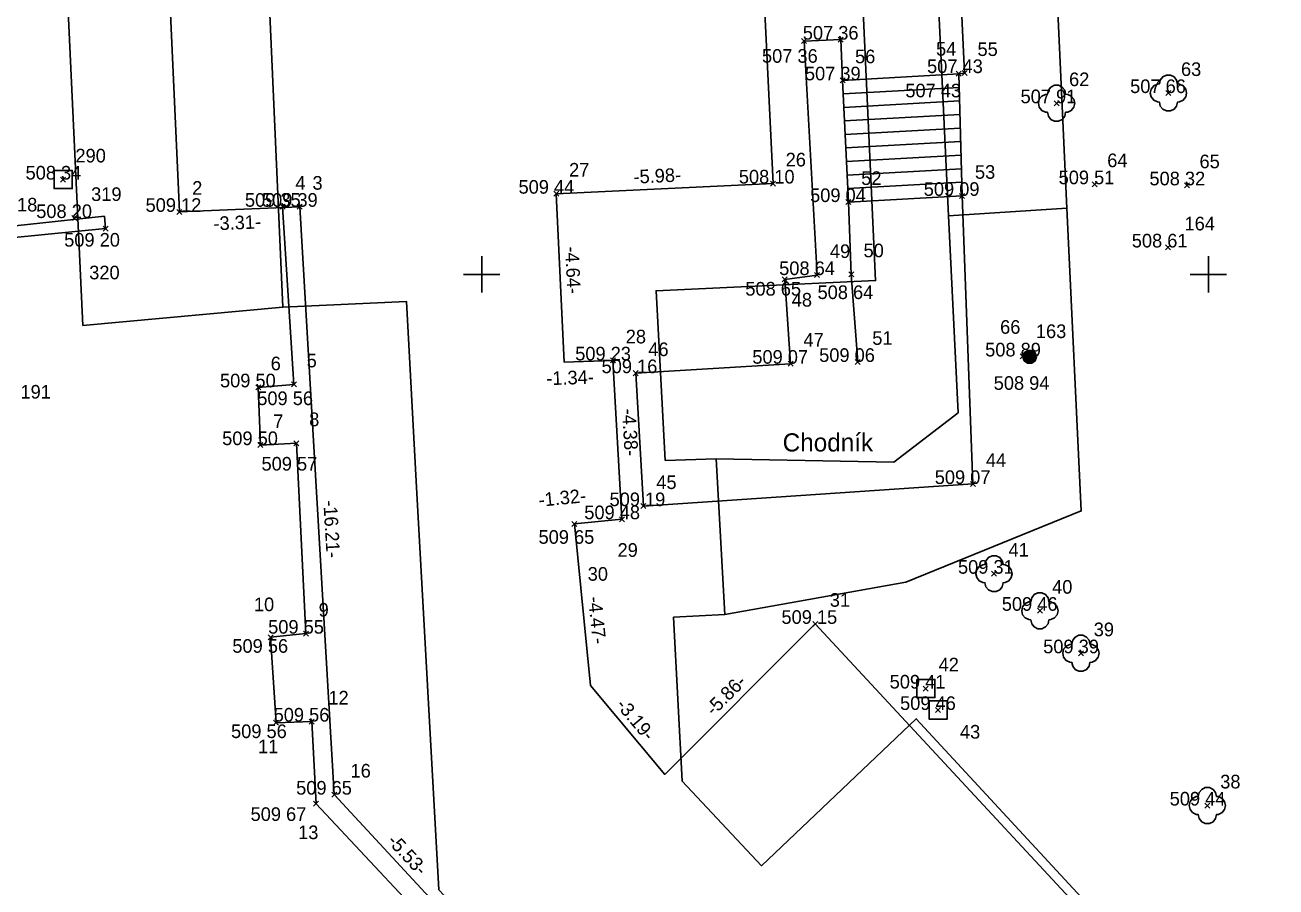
# Model space of a CAD drawing. Extents: x -408550 to -407654, y -1233019 to -1231230.
# Drawn here: x -407992.57 to -407958.14, y -1232056.86 to -1232033.14 of the extents above; entities that cross this region are included whole.
import ezdxf

# ---------------------------------------------------------------- set-up
doc = ezdxf.new("R2010")
doc.units = 0
for name, color, linetype in [('Level 1', 7, 'Continuous'), ('Level 11', 7, 'Continuous'), ('Level 16', 7, 'Continuous'), ('Level 20', 7, 'Continuous'), ('Level 23', 7, 'Continuous'), ('Level 26', 7, 'Continuous'), ('Level 28', 7, 'Continuous'), ('Level 40', 7, 'Continuous'), ('Level 45', 7, 'Continuous'), ('Level 5', 7, 'Continuous')]:
    doc.layers.add(name, color=color, linetype=linetype)

msp = doc.modelspace()

# ---------------------------------------------------------------- linework, layer by layer
at = {"layer": 'Level 1'}
for p, q in [((-407980, -1232039.5), (-407980, -1232040.5)), ((-407960, -1232039.5), (-407960, -1232040.5)), ((-407980.5, -1232040), (-407979.5, -1232040)), ((-407960.5, -1232040), (-407959.5, -1232040))]:
    msp.add_line(p, q, dxfattribs=at)
for points in [[(-407983.55, -1232015.52), (-407983.6, -1232014.52), (-407981.73, -1232014.41), (-407981.67, -1232015.42), (-407970.32, -1232014.9), (-407969.16, -1232040.17), (-407975.2, -1232040.45), (-407974.95, -1232045.12), (-407973.55, -1232045.08), (-407973.31, -1232049.36), (-407974.72, -1232049.44), (-407974.48, -1232053.95), (-407972.3, -1232056.28), (-407968.04, -1232052.23), (-407946.92, -1232075.07), (-407959.14, -1232086.36), (-407980.2, -1232063.57), (-407977.4, -1232060.97), (-407981.18, -1232056.94), (-407981.8, -1232045.69), (-407982.07, -1232040.75), (-407985.47, -1232040.9), (-407986.59, -1232015.66)], [(-407983.6, -1232014.52), (-407983.55, -1232015.52), (-407986.59, -1232015.66), (-407985.47, -1232040.9), (-407982.07, -1232040.75), (-407981.8, -1232045.69), (-407981.18, -1232056.94), (-407977.4, -1232060.97), (-407980.2, -1232063.57), (-407959.14, -1232086.36), (-407946.92, -1232075.07), (-407968.04, -1232052.23), (-407972.3, -1232056.28), (-407974.48, -1232053.95), (-407974.72, -1232049.44), (-407973.31, -1232049.36), (-407973.55, -1232045.08), (-407974.95, -1232045.12), (-407975.2, -1232040.45), (-407969.16, -1232040.17), (-407970.32, -1232014.9), (-407981.67, -1232015.42), (-407981.73, -1232014.41)]]:
    msp.add_lwpolyline(points, close=True, dxfattribs=at)
at = {"layer": 'Level 11'}
msp.add_lwpolyline([(-407989.46, -1232013.01), (-407973.21, -1232012.23), (-407971.98, -1232037.5), (-407977.95, -1232037.78), (-407977.733, -1232042.415), (-407976.39, -1232042.37), (-407976.14, -1232046.74), (-407977.45, -1232046.87), (-407977.009, -1232051.318), (-407974.962, -1232053.765), (-407970.82, -1232049.62), (-407949.71, -1232072.37), (-407961.89, -1232083.71), (-407983.01, -1232060.92), (-407980.3, -1232058.38), (-407984.06, -1232054.32), (-407985.01, -1232038.14), (-407988.32, -1232038.28)], close=True, dxfattribs=at)
at = {"layer": 'Level 16'}
for p, q in [((-407970.07, -1232034.66), (-407966.87, -1232034.48)), ((-407966.86, -1232034.853), (-407970.052, -1232035.032)), ((-407966.85, -1232035.227), (-407970.034, -1232035.404)), ((-407966.84, -1232035.6), (-407970.017, -1232035.777)), ((-407966.83, -1232035.973), (-407969.999, -1232036.149)), ((-407966.82, -1232036.347), (-407969.981, -1232036.521)), ((-407966.81, -1232036.72), (-407969.963, -1232036.893)), ((-407966.8, -1232037.093), (-407969.946, -1232037.266)), ((-407966.79, -1232037.467), (-407969.928, -1232037.638)), ((-407969.91, -1232038.01), (-407966.78, -1232037.84))]:
    msp.add_line(p, q, dxfattribs=at)
for points in [[(-407975.55, -1232046.38), (-407966.48, -1232045.77), (-407966.78, -1232037.84), (-407966.87, -1232034.48), (-407966.71, -1232034.46), (-407967.34, -1232021.13), (-407968.99, -1231990.5), (-407969.06, -1231986.9)], [(-407975.55, -1232046.38), (-407975.76, -1232042.72), (-407971.5, -1232042.46), (-407971.66, -1232040.14), (-407970.77, -1232040.02), (-407971.13, -1232033.58), (-407970.12, -1232033.54), (-407970.07, -1232034.66), (-407969.91, -1232038.01), (-407969.83, -1232040), (-407969.65, -1232042.41)], [(-407985.48, -1232038.14), (-407985.17, -1232043.03), (-407986.15, -1232043.11), (-407986.09, -1232044.7), (-407985.1, -1232044.65), (-407984.84, -1232049.89), (-407985.81, -1232049.99), (-407985.66, -1232052.34), (-407984.68, -1232052.31), (-407984.56, -1232054.57), (-407980.66, -1232058.74)]]:
    msp.add_lwpolyline(points, dxfattribs=at)
for points in [[(-407994.84, -1232017.97), (-407994.55, -1232017.75), (-407994.47, -1232018.24), (-407994.26, -1232023.61), (-407993.53, -1232038.74), (-407990.383, -1232038.402), (-407990.35, -1232038.74), (-407993.79, -1232039.08), (-407994.06, -1232034.84), (-407994.54, -1232023.67)], [(-407966.87, -1232034.48), (-407970.07, -1232034.66), (-407969.91, -1232038.01), (-407966.78, -1232037.84)]]:
    msp.add_lwpolyline(points, close=True, dxfattribs=at)
at = {"layer": 'Level 20'}
for points in [[(-407991.77, -1232037.14), (-407991.27, -1232037.14), (-407991.27, -1232037.64), (-407991.77, -1232037.64)], [(-407968.03, -1232051.15), (-407967.53, -1232051.15), (-407967.53, -1232051.65), (-407968.03, -1232051.65)], [(-407967.69, -1232051.74), (-407967.19, -1232051.74), (-407967.19, -1232052.24), (-407967.69, -1232052.24)]]:
    msp.add_lwpolyline(points, close=True, dxfattribs=at)
at = {"layer": 'Level 23'}
for points in [[(-407971.061, -1232033.649), (-407971.199, -1232033.511)], [(-407971.199, -1232033.649), (-407971.061, -1232033.511)], [(-407970.051, -1232033.609), (-407970.189, -1232033.471)], [(-407970.189, -1232033.609), (-407970.051, -1232033.471)], [(-407966.801, -1232034.549), (-407966.939, -1232034.411)], [(-407966.939, -1232034.549), (-407966.801, -1232034.411)], [(-407966.641, -1232034.529), (-407966.779, -1232034.391)], [(-407966.779, -1232034.529), (-407966.641, -1232034.391)], [(-407970.001, -1232034.729), (-407970.139, -1232034.591)], [(-407970.139, -1232034.729), (-407970.001, -1232034.591)], [(-407964.111, -1232035.359), (-407964.249, -1232035.221)], [(-407964.249, -1232035.359), (-407964.111, -1232035.221)], [(-407961.031, -1232035.079), (-407961.169, -1232034.941)], [(-407961.169, -1232035.079), (-407961.031, -1232034.941)], [(-407991.451, -1232037.459), (-407991.589, -1232037.321)], [(-407991.589, -1232037.459), (-407991.451, -1232037.321)], [(-407971.911, -1232037.569), (-407972.049, -1232037.431)], [(-407972.049, -1232037.569), (-407971.911, -1232037.431)], [(-407963.061, -1232037.589), (-407963.199, -1232037.451)], [(-407963.199, -1232037.589), (-407963.061, -1232037.451)], [(-407960.521, -1232037.619), (-407960.659, -1232037.481)], [(-407960.659, -1232037.619), (-407960.521, -1232037.481)], [(-407977.881, -1232037.849), (-407978.019, -1232037.711)], [(-407978.019, -1232037.849), (-407977.881, -1232037.711)], [(-407969.841, -1232038.079), (-407969.979, -1232037.941)], [(-407969.979, -1232038.079), (-407969.841, -1232037.941)], [(-407966.711, -1232037.909), (-407966.849, -1232037.771)], [(-407966.849, -1232037.909), (-407966.711, -1232037.771)], [(-407988.251, -1232038.349), (-407988.389, -1232038.211)], [(-407988.389, -1232038.349), (-407988.251, -1232038.211)], [(-407985.411, -1232038.209), (-407985.549, -1232038.071)], [(-407985.549, -1232038.209), (-407985.411, -1232038.071)], [(-407984.941, -1232038.209), (-407985.079, -1232038.071)], [(-407985.079, -1232038.209), (-407984.941, -1232038.071)], [(-407991.141, -1232038.519), (-407991.279, -1232038.381)], [(-407991.279, -1232038.519), (-407991.141, -1232038.381)], [(-407990.281, -1232038.809), (-407990.419, -1232038.671)], [(-407990.419, -1232038.809), (-407990.281, -1232038.671)], [(-407961.041, -1232039.329), (-407961.179, -1232039.191)], [(-407961.179, -1232039.329), (-407961.041, -1232039.191)], [(-407970.701, -1232040.089), (-407970.839, -1232039.951)], [(-407970.839, -1232040.089), (-407970.701, -1232039.951)], [(-407969.761, -1232040.069), (-407969.899, -1232039.931)], [(-407969.899, -1232040.069), (-407969.761, -1232039.931)], [(-407971.591, -1232040.209), (-407971.729, -1232040.071)], [(-407971.729, -1232040.209), (-407971.591, -1232040.071)], [(-407976.321, -1232042.439), (-407976.459, -1232042.301)], [(-407976.459, -1232042.439), (-407976.321, -1232042.301)], [(-407971.431, -1232042.529), (-407971.569, -1232042.391)], [(-407971.569, -1232042.529), (-407971.431, -1232042.391)], [(-407969.581, -1232042.479), (-407969.719, -1232042.341)], [(-407969.719, -1232042.479), (-407969.581, -1232042.341)], [(-407965.041, -1232042.329), (-407965.179, -1232042.191)], [(-407965.179, -1232042.329), (-407965.041, -1232042.191)], [(-407964.851, -1232042.339), (-407964.989, -1232042.201)], [(-407964.989, -1232042.339), (-407964.851, -1232042.201)], [(-407975.691, -1232042.789), (-407975.829, -1232042.651)], [(-407975.829, -1232042.789), (-407975.691, -1232042.651)], [(-407986.081, -1232043.179), (-407986.219, -1232043.041)], [(-407986.219, -1232043.179), (-407986.081, -1232043.041)], [(-407985.101, -1232043.099), (-407985.239, -1232042.961)], [(-407985.239, -1232043.099), (-407985.101, -1232042.961)], [(-407986.021, -1232044.769), (-407986.159, -1232044.631)], [(-407986.159, -1232044.769), (-407986.021, -1232044.631)], [(-407985.031, -1232044.719), (-407985.169, -1232044.581)], [(-407985.169, -1232044.719), (-407985.031, -1232044.581)], [(-407966.411, -1232045.839), (-407966.549, -1232045.701)], [(-407966.549, -1232045.839), (-407966.411, -1232045.701)], [(-407975.481, -1232046.449), (-407975.619, -1232046.311)], [(-407975.619, -1232046.449), (-407975.481, -1232046.311)], [(-407977.381, -1232046.939), (-407977.519, -1232046.801)], [(-407977.519, -1232046.939), (-407977.381, -1232046.801)], [(-407976.071, -1232046.809), (-407976.209, -1232046.671)], [(-407976.209, -1232046.809), (-407976.071, -1232046.671)], [(-407965.831, -1232048.309), (-407965.969, -1232048.171)], [(-407965.969, -1232048.309), (-407965.831, -1232048.171)], [(-407964.571, -1232049.329), (-407964.709, -1232049.191)], [(-407964.709, -1232049.329), (-407964.571, -1232049.191)], [(-407970.751, -1232049.689), (-407970.889, -1232049.551)], [(-407970.889, -1232049.689), (-407970.751, -1232049.551)], [(-407985.741, -1232050.059), (-407985.879, -1232049.921)], [(-407985.879, -1232050.059), (-407985.741, -1232049.921)], [(-407984.771, -1232049.959), (-407984.909, -1232049.821)], [(-407984.909, -1232049.959), (-407984.771, -1232049.821)], [(-407963.441, -1232050.499), (-407963.579, -1232050.361)], [(-407963.579, -1232050.499), (-407963.441, -1232050.361)], [(-407967.711, -1232051.469), (-407967.849, -1232051.331)], [(-407967.849, -1232051.469), (-407967.711, -1232051.331)], [(-407967.371, -1232052.059), (-407967.509, -1232051.921)], [(-407967.509, -1232052.059), (-407967.371, -1232051.921)], [(-407985.591, -1232052.409), (-407985.729, -1232052.271)], [(-407985.729, -1232052.409), (-407985.591, -1232052.271)], [(-407984.611, -1232052.379), (-407984.749, -1232052.241)], [(-407984.749, -1232052.379), (-407984.611, -1232052.241)], [(-407984.491, -1232054.639), (-407984.629, -1232054.501)], [(-407984.629, -1232054.639), (-407984.491, -1232054.501)], [(-407983.991, -1232054.389), (-407984.129, -1232054.251)], [(-407984.129, -1232054.389), (-407983.991, -1232054.251)], [(-407959.961, -1232054.689), (-407960.099, -1232054.551)], [(-407960.099, -1232054.689), (-407959.961, -1232054.551)]]:
    msp.add_lwpolyline(points, dxfattribs=at)
at = {"layer": 'Level 28'}
for points in [[(-407960.6, -1232035.01), (-407960.625, -1232035.118), (-407960.694, -1232035.206), (-407960.794, -1232035.254), (-407960.85, -1232035.26), (-407960.875, -1232035.368), (-407960.944, -1232035.456), (-407961.044, -1232035.504), (-407961.156, -1232035.504), (-407961.256, -1232035.456), (-407961.325, -1232035.368), (-407961.35, -1232035.26), (-407961.406, -1232035.254), (-407961.506, -1232035.206), (-407961.575, -1232035.118), (-407961.6, -1232035.01), (-407961.575, -1232034.902), (-407961.506, -1232034.814), (-407961.406, -1232034.766), (-407961.35, -1232034.76), (-407961.325, -1232034.652), (-407961.256, -1232034.564), (-407961.156, -1232034.516), (-407961.044, -1232034.516), (-407960.944, -1232034.564), (-407960.875, -1232034.652), (-407960.85, -1232034.76), (-407960.794, -1232034.766), (-407960.694, -1232034.814), (-407960.625, -1232034.902)], [(-407963.68, -1232035.29), (-407963.705, -1232035.399), (-407963.774, -1232035.486), (-407963.874, -1232035.534), (-407963.93, -1232035.54), (-407963.955, -1232035.649), (-407964.024, -1232035.736), (-407964.124, -1232035.784), (-407964.236, -1232035.784), (-407964.336, -1232035.736), (-407964.405, -1232035.649), (-407964.43, -1232035.54), (-407964.486, -1232035.534), (-407964.586, -1232035.486), (-407964.655, -1232035.399), (-407964.68, -1232035.29), (-407964.655, -1232035.182), (-407964.586, -1232035.095), (-407964.486, -1232035.046), (-407964.43, -1232035.04), (-407964.405, -1232034.932), (-407964.336, -1232034.845), (-407964.236, -1232034.796), (-407964.124, -1232034.796), (-407964.024, -1232034.845), (-407963.955, -1232034.932), (-407963.93, -1232035.04), (-407963.874, -1232035.046), (-407963.774, -1232035.095), (-407963.705, -1232035.182)], [(-407965.4, -1232048.24), (-407965.425, -1232048.348), (-407965.494, -1232048.436), (-407965.594, -1232048.484), (-407965.65, -1232048.49), (-407965.675, -1232048.598), (-407965.744, -1232048.686), (-407965.844, -1232048.734), (-407965.956, -1232048.734), (-407966.056, -1232048.686), (-407966.125, -1232048.598), (-407966.15, -1232048.49), (-407966.206, -1232048.484), (-407966.306, -1232048.436), (-407966.375, -1232048.348), (-407966.4, -1232048.24), (-407966.375, -1232048.132), (-407966.306, -1232048.044), (-407966.206, -1232047.996), (-407966.15, -1232047.99), (-407966.125, -1232047.882), (-407966.056, -1232047.794), (-407965.956, -1232047.746), (-407965.844, -1232047.746), (-407965.744, -1232047.794), (-407965.675, -1232047.882), (-407965.65, -1232047.99), (-407965.594, -1232047.996), (-407965.494, -1232048.044), (-407965.425, -1232048.132)], [(-407964.14, -1232049.26), (-407964.165, -1232049.368), (-407964.234, -1232049.456), (-407964.334, -1232049.504), (-407964.39, -1232049.51), (-407964.415, -1232049.618), (-407964.484, -1232049.706), (-407964.584, -1232049.754), (-407964.696, -1232049.754), (-407964.796, -1232049.706), (-407964.865, -1232049.618), (-407964.89, -1232049.51), (-407964.946, -1232049.504), (-407965.046, -1232049.456), (-407965.115, -1232049.368), (-407965.14, -1232049.26), (-407965.115, -1232049.152), (-407965.046, -1232049.064), (-407964.946, -1232049.016), (-407964.89, -1232049.01), (-407964.865, -1232048.902), (-407964.796, -1232048.814), (-407964.696, -1232048.766), (-407964.584, -1232048.766), (-407964.484, -1232048.814), (-407964.415, -1232048.902), (-407964.39, -1232049.01), (-407964.334, -1232049.016), (-407964.234, -1232049.064), (-407964.165, -1232049.152)], [(-407963.01, -1232050.43), (-407963.035, -1232050.538), (-407963.104, -1232050.625), (-407963.204, -1232050.674), (-407963.26, -1232050.68), (-407963.285, -1232050.788), (-407963.354, -1232050.875), (-407963.454, -1232050.924), (-407963.566, -1232050.924), (-407963.666, -1232050.875), (-407963.735, -1232050.788), (-407963.76, -1232050.68), (-407963.816, -1232050.674), (-407963.916, -1232050.625), (-407963.985, -1232050.538), (-407964.01, -1232050.43), (-407963.985, -1232050.321), (-407963.916, -1232050.234), (-407963.816, -1232050.186), (-407963.76, -1232050.18), (-407963.735, -1232050.071), (-407963.666, -1232049.984), (-407963.566, -1232049.936), (-407963.454, -1232049.936), (-407963.354, -1232049.984), (-407963.285, -1232050.071), (-407963.26, -1232050.18), (-407963.204, -1232050.186), (-407963.104, -1232050.234), (-407963.035, -1232050.321)], [(-407959.53, -1232054.62), (-407959.555, -1232054.729), (-407959.624, -1232054.816), (-407959.724, -1232054.864), (-407959.78, -1232054.87), (-407959.805, -1232054.979), (-407959.874, -1232055.066), (-407959.974, -1232055.114), (-407960.086, -1232055.114), (-407960.186, -1232055.066), (-407960.255, -1232054.979), (-407960.28, -1232054.87), (-407960.336, -1232054.864), (-407960.436, -1232054.816), (-407960.505, -1232054.729), (-407960.53, -1232054.62), (-407960.505, -1232054.512), (-407960.436, -1232054.425), (-407960.336, -1232054.376), (-407960.28, -1232054.37), (-407960.255, -1232054.262), (-407960.186, -1232054.175), (-407960.086, -1232054.126), (-407959.974, -1232054.126), (-407959.874, -1232054.175), (-407959.805, -1232054.262), (-407959.78, -1232054.37), (-407959.724, -1232054.376), (-407959.624, -1232054.425), (-407959.555, -1232054.512)]]:
    msp.add_lwpolyline(points, close=True, dxfattribs=at)
for points in [[(-407961.112, -1232035.01), (-407961.1, -1232035.01), (-407961.087, -1232035.01)], [(-407964.192, -1232035.29), (-407964.18, -1232035.29), (-407964.168, -1232035.29)], [(-407965.913, -1232048.24), (-407965.9, -1232048.24), (-407965.888, -1232048.24)], [(-407964.652, -1232049.26), (-407964.64, -1232049.26), (-407964.628, -1232049.26)], [(-407963.522, -1232050.43), (-407963.51, -1232050.43), (-407963.498, -1232050.43)], [(-407960.043, -1232054.62), (-407960.03, -1232054.62), (-407960.018, -1232054.62)]]:
    msp.add_lwpolyline(points, dxfattribs=at)
at = {"layer": 'Level 45'}
msp.add_lwpolyline([(-407964.978, -1232042.092), (-407964.862, -1232042.092), (-407964.768, -1232042.16), (-407964.732, -1232042.27), (-407964.768, -1232042.38), (-407964.862, -1232042.448), (-407964.978, -1232042.448), (-407965.072, -1232042.38), (-407965.108, -1232042.27), (-407965.072, -1232042.16), (-407964.978, -1232042.092), (-407964.965, -1232042.105), (-407964.875, -1232042.105), (-407964.815, -1232042.135), (-407965.025, -1232042.135), (-407965.055, -1232042.165), (-407964.785, -1232042.165), (-407964.785, -1232042.195), (-407965.055, -1232042.195), (-407965.071, -1232042.225), (-407964.77, -1232042.225), (-407964.755, -1232042.255), (-407965.085, -1232042.255), (-407965.085, -1232042.285), (-407964.755, -1232042.285), (-407964.767, -1232042.315), (-407965.072, -1232042.315), (-407965.07, -1232042.345), (-407964.767, -1232042.345), (-407964.785, -1232042.375), (-407965.055, -1232042.375), (-407965.025, -1232042.405), (-407964.815, -1232042.405), (-407964.856, -1232042.435), (-407964.983, -1232042.435)], dxfattribs=at)
at = {"layer": 'Level 5'}
for p, q in [((-407966.08, -1231990.2), (-407963.9, -1232038.18)), ((-407967.15, -1232038.39), (-407968.26, -1232014.87)), ((-407990.98, -1232041.41), (-407992.15, -1232016.06)), ((-407963.9, -1232038.18), (-407967.15, -1232038.39)), ((-407985.47, -1232040.9), (-407990.98, -1232041.41))]:
    msp.add_line(p, q, dxfattribs=at)
for points in [[(-407963.9, -1232038.18), (-407963.5, -1232046.51), (-407968.33, -1232048.47), (-407973.31, -1232049.36)], [(-407973.55, -1232045.08), (-407968.66, -1232045.17), (-407966.89, -1232043.81), (-407967.15, -1232038.39)]]:
    msp.add_lwpolyline(points, dxfattribs=at)

# ---------------------------------------------------------------- texts
at = {"layer": 'Level 1'}
for s, rotation, p in [('-5.98-', 2.6929, (-407975.815, -1232037.505)), ('-3.31-', 2.4064, (-407987.376, -1232038.79)), ('-4.64-', 272.6812, (-407977.706, -1232039.238)), ('-1.34-', 1.8908, (-407978.218, -1232043.052)), ('-4.38-', 273.2542, (-407976.138, -1232043.705)), ('-16.21-', 273.3688, (-407984.36, -1232046.229)), ('-1.32-', 5.6723, (-407978.418, -1232046.4)), ('-4.47-', 275.6606, (-407977.074, -1232048.886)), ('-5.86-', 45.0345, (-407973.617, -1232052.172)), ('-3.19-', 309.9235, (-407976.324, -1232051.865)), ('-5.53-', 312.7883, (-407982.623, -1232055.614))]:
    msp.add_text(s, height=0.375, rotation=rotation, dxfattribs=at).set_placement(p)
at = {"layer": 'Level 26'}
for s, p in [('56', (-407969.726, -1232034.19)), ('54', (-407967.497, -1232033.98)), ('55', (-407966.356, -1232033.99)), ('63', (-407960.756, -1232034.54)), ('62', (-407963.836, -1232034.82)), ('290', (-407991.181, -1232036.92)), ('27', (-407977.596, -1232037.31)), ('26', (-407971.636, -1232037.03)), ('64', (-407962.786, -1232037.05)), ('65', (-407960.246, -1232037.08)), ('4', (-407985.128, -1232037.67)), ('3', (-407984.658, -1232037.67)), ('52', (-407969.556, -1232037.54)), ('53', (-407966.426, -1232037.37)), ('319', (-407990.749, -1232037.98)), ('2', (-407987.968, -1232037.81)), ('318', (-407993.067, -1232038.27)), ('164', (-407960.658, -1232038.79)), ('49', (-407970.417, -1232039.55)), ('50', (-407969.492, -1232039.53)), ('320', (-407990.802, -1232040.137)), ('48', (-407971.468, -1232040.888)), ('66', (-407965.734, -1232041.636)), ('163', (-407964.749, -1232041.754)), ('28', (-407976.036, -1232041.9)), ('47', (-407971.146, -1232041.99)), ('51', (-407969.251, -1232041.94)), ('46', (-407975.416, -1232042.25)), ('6', (-407985.808, -1232042.64)), ('5', (-407984.818, -1232042.56)), ('191', (-407992.694, -1232043.42)), ('8', (-407984.748, -1232044.18)), ('7', (-407985.738, -1232044.23)), ('44', (-407966.126, -1232045.3)), ('45', (-407975.196, -1232045.91)), ('29', (-407976.262, -1232047.775)), ('41', (-407965.501, -1232047.77)), ('30', (-407977.084, -1232048.433)), ('40', (-407964.302, -1232048.79)), ('10', (-407986.269, -1232049.271)), ('31', (-407970.421, -1232049.15)), ('9', (-407984.489, -1232049.42)), ('39', (-407963.157, -1232049.96)), ('42', (-407967.426, -1232050.93)), ('12', (-407984.219, -1232051.84)), ('43', (-407966.839, -1232052.778)), ('11', (-407986.155, -1232053.183)), ('16', (-407983.61, -1232053.85)), ('38', (-407959.676, -1232054.15)), ('13', (-407985.053, -1232055.546))]:
    msp.add_text(s, height=0.375, dxfattribs=at).set_placement(p)
at = {"layer": 'Level 28'}
msp.add_text('Chodník', height=0.5, dxfattribs=at).set_placement((-407971.718, -1232044.876))
at = {"layer": 'Level 40'}
for s, p in [('507 36', (-407971.164, -1232033.54)), ('507 36', (-407972.287, -1232034.176)), ('507 43', (-407967.744, -1232034.46)), ('507 39', (-407971.105, -1232034.66)), ('507 43', (-407968.342, -1232035.128)), ('507 66', (-407962.155, -1232035.01)), ('507 91', (-407965.171, -1232035.29)), ('508 34', (-407992.554, -1232037.39)), ('508 10', (-407972.924, -1232037.5)), ('509 51', (-407964.123, -1232037.52)), ('508 32', (-407961.624, -1232037.55)), ('509 44', (-407978.987, -1232037.78)), ('509 04', (-407970.963, -1232038.01)), ('509 09', (-407967.835, -1232037.84)), ('509 12', (-407989.251, -1232038.28)), ('509 35', (-407986.517, -1232038.14)), ('509 39', (-407986.048, -1232038.14)), ('508 20', (-407992.26, -1232038.45)), ('509 20', (-407991.491, -1232039.237)), ('508 61', (-407962.11, -1232039.26)), ('508 64', (-407971.814, -1232040.02)), ('508 65', (-407972.746, -1232040.585)), ('508 64', (-407970.758, -1232040.68)), ('509 23', (-407977.427, -1232042.37)), ('509 07', (-407972.553, -1232042.46)), ('509 06', (-407970.713, -1232042.41)), ('508 89', (-407966.145, -1232042.26)), ('509 16', (-407976.701, -1232042.72)), ('509 50', (-407987.203, -1232043.11)), ('508 94', (-407965.91, -1232043.178)), ('509 56', (-407986.177, -1232043.599)), ('509 50', (-407987.143, -1232044.7)), ('509 57', (-407986.06, -1232045.401)), ('509 07', (-407967.533, -1232045.77)), ('509 19', (-407976.482, -1232046.38)), ('509 48', (-407977.177, -1232046.74)), ('509 65', (-407978.436, -1232047.416)), ('509 31', (-407966.893, -1232048.24)), ('509 46', (-407965.687, -1232049.26)), ('509 15', (-407971.751, -1232049.62)), ('509 55', (-407985.877, -1232049.89)), ('509 56', (-407986.863, -1232050.416)), ('509 39', (-407964.548, -1232050.43)), ('509 41', (-407968.773, -1232051.4)), ('509 46', (-407968.487, -1232051.99)), ('509 56', (-407985.727, -1232052.31)), ('509 56', (-407986.899, -1232052.764)), ('509 65', (-407985.107, -1232054.32)), ('509 44', (-407961.067, -1232054.62)), ('509 67', (-407986.361, -1232055.045))]:
    msp.add_text(s, height=0.375, dxfattribs=at).set_placement(p)

doc.saveas('drawing.dxf')
